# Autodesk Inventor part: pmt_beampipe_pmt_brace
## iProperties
Shininess: 64.0
Length Units: 11269
Angle Units: 11279
Time Units: 11290
Mass Units: 11283
Length Display Precision: 3
Angle Display Precision: 2
Compacted: True
Part Number: pmt_beampipe_pmt_brace
Document SubType Name: Modeling
Created: 2004-08
Designer: John Blackburn
Manufacturer: Standard
Standards Organization: Custom
Material: Aluminum-6061
Density: 0.0
Volumn: 0.0
Area: 0.0
PropertySet Name: Model Information
Control State: 0
Master: False
Checked Out: False
Author: John Blackburn
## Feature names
1. Extrusion1
2. Extrusion2
3. Hole1
4. Hole4
